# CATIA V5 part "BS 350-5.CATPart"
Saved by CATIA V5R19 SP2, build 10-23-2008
Part number: BS 300-5
Bounding box of the stored display mesh (mm): x -15.868 to 15.868, y -15.868 to 15.868, z 0 to 40
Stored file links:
  C:\Users\Bora\Desktop\3D Katı model\BS serisi\BS 300\BS 300-5.CATPart
  C:\Program Files\Dassault Systemes\B19\intel_a\reffiles\standard\MetricThickPitch.txt
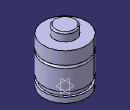
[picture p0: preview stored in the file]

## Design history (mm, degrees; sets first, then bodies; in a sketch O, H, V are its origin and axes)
Body1 (main body)
  Sketch1 on yz-plane, origin (0, 0, 0), H (0, 1, 0), V (0, 0, 1)
    point P1 (8, 39)
    point P3 (8, 39)
    point P5 (16, 24.5)
    point P6 (16, 22.5)
    point P9 (16, 24.5)
    point P14 (16, 22.5)
    line L1 (8, 39) -> (8, 34)
    arc A1 centre (7, 39) radius 1 from (8, 39) to (7, 40) ccw
    arc A2 centre (16, 23.5) radius 1 from (16, 24.5) to (16, 22.5) ccw
    line L2 (16, 0) -> (16, 4)
    line L3 (16, 24.5) -> (16, 34)
    line L4 (14.5, 7.5) -> (14.5, 4)
    line L5 (16, 7.5) -> (16, 22.5)
    line L6 (7, 40) -> (0, 40)
    point P15 (0, 40)
    line L7 (8, 34) -> (16, 34)
    line L8 (0, 0) -> (16, 0)
    line L9 (14.5, 7.5) -> (16, 7.5)
    line L10 (14.5, 4) -> (16, 4)
    tangency: L6 A1
    coincidence: P15 V, P1 P3, P5 P9, P6 P14
    horizontal: L7 H, L8 H, L9 H, L10 H
  Shaft1: profile Sketch1, axis Sketch1.V, angle 360
  Sketch2 on face of Shaft1 from Sketch1.L8, origin (0, 0, 0), H (1, 0, 0), V (0, -1, 0)
    point P1 (0, 0)
  Hole1: placed by Sketch2, at (0, 0, 0) direction (0, 0, 1), diameter 6.647, depth 4, threaded "M8", thread diameter 8, thread depth 4, pitch 1.25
